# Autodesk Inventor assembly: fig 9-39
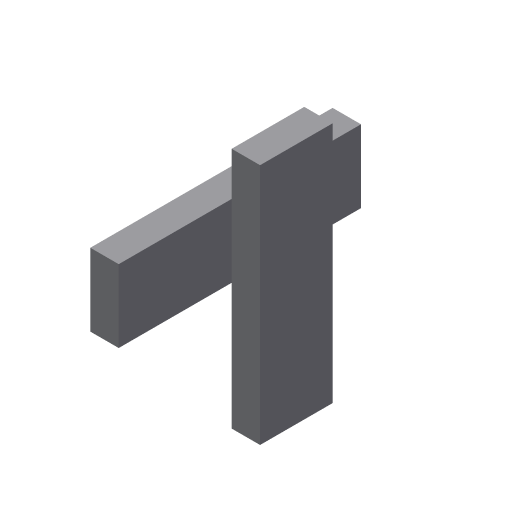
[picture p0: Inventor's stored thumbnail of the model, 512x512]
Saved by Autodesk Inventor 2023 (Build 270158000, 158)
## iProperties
Created: 2013-07
Part Number: fig 9-39
Document SubType Name: Assembly
Designer: CADCIM
Author: CADCIM
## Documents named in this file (2)
- D:\PROJECTS\Project 2022\Autodesk Inventor For Professional 2023\RESOURCES INVENTOR 2023\RESOURCES INVENTOR 2023\Inventor_2023_Part\Inventor_2023_Part\c09_Inv_2023_prt\fig 9-40.iam
- D:\PROJECTS\Project 2022\Autodesk Inventor For Professional 2023\RESOURCES INVENTOR 2023\RESOURCES INVENTOR 2023\Inventor_2023_Part\Inventor_2023_Part\c09_Inv_2023_prt\12.ipt
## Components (2 placed, 1 different names)
1. 12:1
2. 12:2
